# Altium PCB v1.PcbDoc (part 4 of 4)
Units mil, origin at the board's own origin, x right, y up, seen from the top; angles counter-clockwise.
Board outline 3043 x 5109 mil, 2 copper layers (Top Layer, Bottom Layer), stack 62 mil thick; 379 components, 219 nets, 963 pads, 1099 vias.
Unrouted connection lines stored in the file: 1.
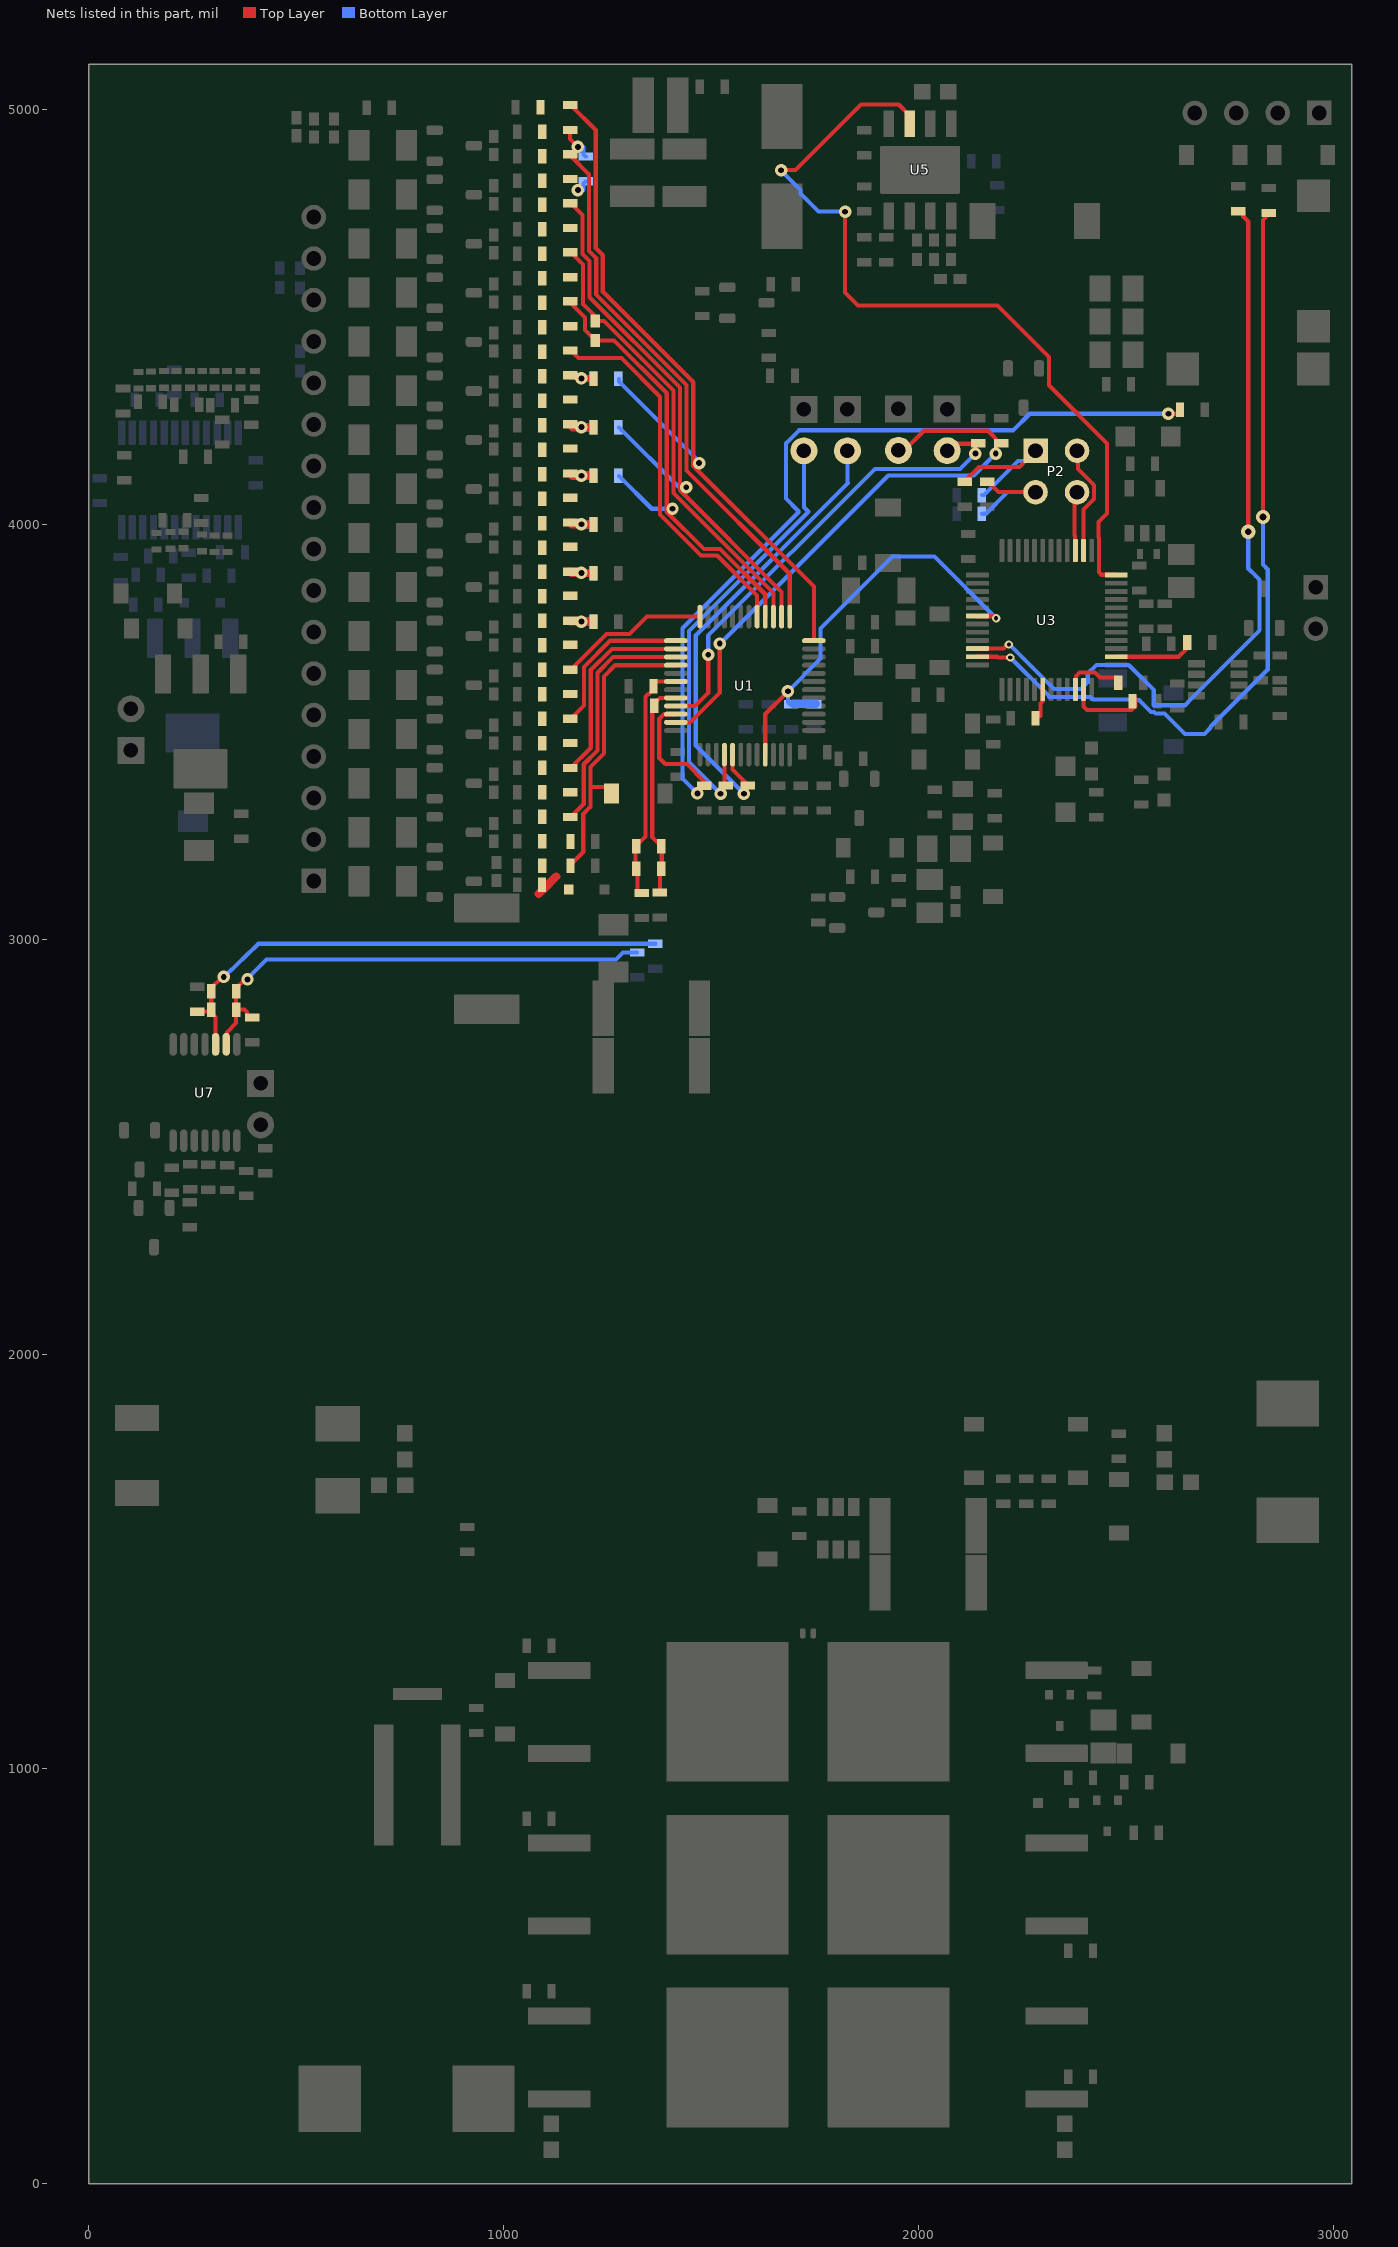
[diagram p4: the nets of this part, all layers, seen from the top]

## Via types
v1: diameter 30, hole 14, Top Layer to Bottom Layer, 1049 vias
v2: diameter 20, hole 10, Top Layer to Bottom Layer, 38 vias
v3: diameter 19.68, hole 7.87, Top Layer to Bottom Layer, tented both sides, 4 vias
v4: diameter 19.68, hole 7.87, Top Layer to Bottom Layer, 4 vias
v5: diameter 34, hole 16, Top Layer to Bottom Layer, 3 vias
v6: diameter 26, hole 10, Top Layer to Bottom Layer, 1 vias

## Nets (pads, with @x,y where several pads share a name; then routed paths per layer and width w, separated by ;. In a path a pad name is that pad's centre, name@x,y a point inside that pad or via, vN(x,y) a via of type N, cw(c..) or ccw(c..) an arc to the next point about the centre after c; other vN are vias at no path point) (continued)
POW_EN: U3.12 U5.3 | length 1975.5
  Top Layer w10: v1(1668,4853) 1668.94,4853.94 1703,4853.94 1860.41,5011.35 1951.56,5011.35 1978,4984.91 U5.3@1978,4965.22 ; v1(1822.41,4753.35) 1822.41,4558.35 1853.41,4527.35 2189.41,4527.35 2313.41,4403.35 2313.41,4334.97 2453.94,4194.45 2453.94,4026.25 2432.89,4005.2 2432.89,3968.38 2434.41,3966.86 2434.41,3884.35 2440.41,3878.35 2475.04,3878.35 U3.12@2475.95,3877.44
  Bottom Layer w10: v1(1668,4853) 1715.12,4805.88 1715.12,4796.64 1758.41,4753.35 v1@1809.41,4753.35
PTC_Pull: R97.2 U3.42 | length 81
  Top Layer w10: R97.2@2281.25,3532.04 2281.25,3532.9 2286.25,3537.9 2292.91,3537.9 2292.91,3567.78 2297.88,3572.75 2297.88,3600.95 U3.42@2298.78,3601.85
RXD: R101.2 U3.47 | length 192
  Top Layer w10: U3.47@2397.21,3601.85 2397.21,3560.55 2405.27,3552.49 2512.61,3552.49 2522.41,3562.29 R101.2@2522.41,3580.35
SBCLK: R107.1 U3.35 | length 1953.7
  Top Layer w10: U3.35@2141.3,3680.59 2188.55,3680.59 2190.14,3679 v2(2220.35,3679) ; v5(2829.41,4017.35) 2829.41,4733.33 R107.1@2844.88,4748.8
  Bottom Layer w10: v2(2220.35,3679) 2314.49,3584.87 2314.49,3583.65 2413.52,3583.65 2419.18,3578 2518.22,3578 2519.87,3576.35 2531.18,3576.35 2559.72,3547.8 2567.04,3547.8 2570.91,3543.94 2592.05,3543.94 2641.64,3494.35 2688.18,3494.35 2703.41,3509.58 2703.41,3512 2841,3649.59 2841,3891.13 2829.41,3902.72 v5(2829.41,4017.35)
SBIO: R108.1 U3.34 | length 1938.5
  Top Layer w10: U3.34@2141.3,3700.28 2204.57,3700.28 2214.29,3710 v2(2217,3710) ; R108.1@2769.41,4754.35 2776.91,4754.35 2781.91,4749.35 2781.91,4741.85 2794,4729.76 v5(2794,3982)
  Bottom Layer w10: v2(2217,3710) 2219.05,3710 2326.32,3602.74 2391.4,3602.74 2407.02,3618.35 2407.02,3639.97 2427.99,3660.95 2506.01,3660.95 2566.35,3600.61 2566.35,3563.8 2641.98,3563.8 2648.43,3570.25 2648.43,3571.35 ; 2648.42,3571.35 2821.41,3744.33 2821.41,3866.12 2813.41,3874.12 2794,3893.52 v5(2794,3982)
SCL: P2.1 R89.1 R104.2 | length 338.9
  Top Layer w10: R104.2@2110.41,4103.84 2144.91,4138.35 2242.41,4138.35 P2.1@2281.41,4177.35
  Bottom Layer w10: R89.1@2152.91,4070.35 2157.04,4070.35 2239.04,4152.35 P2.1@2256.41,4152.35
SCL_MCU: P2.2 U3.14 | length 267.9
  Top Layer w10: P2.2@2381.41,4177.35 2383.25,4175.5 2383.25,4132.82 2421.94,4094.13 2421.94,4060.56 2397.21,4035.83 U3.14@2397.21,3936.5
SDA: P2.3 R90.1 R103.2 | length 295.4
  Top Layer w10: R103.2@2165.41,4103.84 2191.91,4077.35 P2.3@2281.41,4077.35
  Bottom Layer w10: R90.1@2152.91,4025.35 2161.85,4025.35 2213.85,4077.35 P2.3@2281.41,4077.35 P2.3@2268.41,4064.35
SDA_MCU: P2.4 U3.15 | length 144.1
  Top Layer w10: U3.15@2377.52,3936.5 2376.62,3937.41 2376.62,3972.13 2375.55,3973.2 2375.55,4071.49 P2.4@2381.41,4077.35
SHUT: C25.1 R92.2 U1.33 U3.30 | length 1055.1
  Top Layer w10: U1.33@1629.96,3444.74 1629.96,3542.9 v1(1684.41,3597.35) ; U3.30@2141.3,3779.02 2142.21,3778.11 2178.94,3778.11 2183.7,3773.35 v2(2186.41,3773.35)
  Bottom Layer w10: C25.1@1692.79,3565.84 1689.41,3565.84 1684.41,3570.84 v1(1684.41,3597.35) 1763.41,3676.35 1763.41,3748.97 1936.78,3922.35 2037.41,3922.35 v2(2186.41,3773.35)
  Bottom Layer w20: C25.1@1696.79,3567.34 R92.2@1751.41,3567.34
SRN: C27.2 C29.2 C33.2 R87.2 U1.20 | length 524.8
  Top Layer w10: R87.2@1375.91,3113.84 1375.91,3164.85 1380.4,3169.35 1380.4,3223.35 1357.41,3246.34 1357.41,3562.35 1376.61,3581.55 U1.20@1414.41,3581.55
SRN1: C81.2 C83.2 C84.2 R165.2 U7.10 | length 1289.8
  Top Layer w10: C81.2@260.59,2825.35 289.59,2825.35 C84.2@294.59,2830.35 ; U7.10@305.18,2746.49 305.18,2812.26 294.59,2822.85 C84.2@294.59,2830.35 ; v1(325,2909) 321.74,2909 294.59,2881.85 C83.2@294.59,2874.35 C84.2@294.59,2830.35
  Bottom Layer w10: v1(325,2909) 408,2989 R165.2@1365,2989
SRP: C28.2 C29.1 C33.1 R88.2 U1.18 | length 578.7
  Top Layer w10: R88.2@1321.91,3113.84 1321.91,3164.85 1317.41,3169.35 1317.41,3223.35 1341.41,3247.35 1341.41,3584.4 1347.85,3590.85 1349.41,3590.85 1360.41,3601.85 C28.2@1360.41,3609.35 1360.41,3615.92 1365.41,3620.92 U1.18@1414.41,3620.92
SRP1: C82.2 C83.1 C84.1 R166.2 U7.9 | length 1199.2
  Top Layer w10: U7.9@330.77,2746.49 332.24,2747.97 332.24,2775.51 354.59,2797.85 C84.1@354.59,2830.35 ; v1(382,2903) 378.17,2899.17 371.91,2899.17 354.59,2881.85 C83.1@354.59,2874.35 C84.1@354.59,2830.35 ; C82.2@393.59,2811.35 386.09,2811.35 381.09,2816.35 381.09,2823.85 374.59,2830.35 C84.1@354.59,2830.35
  Bottom Layer w10: v1@381,2904 428,2951 1270,2951 1287,2968 R166.2@1321,2968
STB: R100.2 U3.2 | length 186.4
  Top Layer w10: U3.2@2475.95,3680.59 2626.16,3680.59 2646.41,3700.85 R100.2@2646.41,3708.35
TS1: C23.1 RT1.2 U1.21 | length 1161.7
  Top Layer w10: U1.21@1414.41,3561.87 1460.93,3561.87 1492.41,3593.35 v1(1492.41,3685.35) ; RT1.2@2068.41,4177.35 2084.93,4193.86 C23.1@2139.91,4193.86 ; v1(2136.41,4170.35) 2136.41,4190.36 C23.1@2139.91,4193.86 ; C23.1@2143.41,4193.86 C23.1@2139.91,4193.86
  Bottom Layer w10: v1(1492.41,3685.35) 1492.41,3731.35 1894.41,4133.35 2099.41,4133.35 v1(2136.41,4170.35)
TS2: C26.1 RT2.2 U1.23 | length 1410
  Top Layer w10: U1.23@1414.26,3522.35 U1.23@1414.41,3522.5 1448.93,3522.5 1520.41,3593.97 v1(1520.41,3712.35) ; RT2.2@1964.41,4177.35 2012.41,4225.35 2166.93,4225.35 2198.41,4193.86 2189.41,4193.86 2185.91,4190.36 2185.91,4170.85 v1(2185.41,4170.35)
  Bottom Layer w10: v1(1520.41,3712.35) 1521.41,3712.35 1926.41,4117.35 2132.41,4117.35 v1(2185.41,4170.35)
TS3: C32.1 RT3.2 U1.28 | length 1080.8
  Top Layer w10: v1(1522.41,3350.35) 1522.41,3365.35 1527.41,3370.35 C32.1@1534.41,3370.35 ; C32.1@1531.54,3374.72 U1.28@1531.54,3444.74
  Bottom Layer w10: v1(1522.41,3350.35) 1446.41,3426.35 1446.41,3742.72 1733.85,4030.15 1723,4041 RT3.2@1723,4177
TS4: C35.1 RT4.2 U1.29 | length 1144.3
  Top Layer w10: U1.29@1551.22,3444.74 1551.22,3408.97 1587.41,3372.78 1585.85,3372.78 1578.41,3365.35 1578.41,3356.14 1581.55,3353 1581.06,3353 v1(1578.41,3350.35)
  Bottom Layer w10: v1(1578.41,3350.35) 1462.41,3466.35 1462.41,3732.35 1829.53,4099.47 1828,4101 RT4.2@1828,4177
TXD: R102.2 U3.46 | length 140.6
  Top Layer w10: U3.46@2377.52,3601.85 2378.43,3602.76 2378.43,3633.51 2387.27,3642.35 2424.28,3642.35 2436.28,3630.35 R102.2@2478.41,3630.35
VC0: C1.1 D9.1 D10.1 R17.2 R18.2 U1.16 | length 836.8
  Top Layer w10: C1.1@1158.91,3177.35 1191.22,3209.65 1191.22,3302.03 1208.41,3319.22 1208.41,3367 ; D10.1@1259.53,3351 1259.53,3353.99 1246.52,3367 1208.41,3367 ; U1.16@1414.41,3660.29 1268.35,3660.29 1241.41,3633.35 1241.41,3447.88 1208.41,3414.88 1208.41,3367
  Top Layer w20: 1083.91,3108.91 1126,3151 R17.2@1095.25,3120.25
VC1: C2.2 C9.1 R19.2 R20.2 U1.15 | length 581.3
  Top Layer w10: C2.2@1159.41,3292.85 1192.41,3325.85 1192.41,3421.51 1225.41,3454.51 1225.41,3642.09 1263.29,3679.98 U1.15@1414.41,3679.98
VC2: C2.1 C3.2 R21.2 R22.2 U1.14 | length 484.4
  Top Layer w10: C3.2@1159.41,3411.14 1209.41,3461.14 1209.41,3648.72 1260.35,3699.66 U1.14@1414.41,3699.66
VC3: C3.1 C4.2 R23.2 R24.2 U1.13 | length 388.1
  Top Layer w10: C4.2@1159.41,3529.42 1193.41,3563.42 1193.41,3656.35 1256.41,3719.35 U1.13@1414.41,3719.35
VC4: C4.1 C5.2 R25.2 R26.2 U1.12 | length 366.8
  Top Layer w10: C5.2@1159.41,3647.71 1247.05,3735.35 1302.41,3735.35 1344.48,3777.42 U1.12@1472.48,3777.42
VC5: C5.1 C6.2 R27.2 R28.2 R67.1 R69.2 | length 83.6
  Top Layer w20: C6.2@1160.06,3765.35 v1(1186.68,3765.35) R69.2@1214.41,3765.35
  Bottom Layer w20: v1(1186.68,3765.35) R67.1@1215.91,3765.35
VC6: C6.1 C7.2 R29.2 R30.2 R64.1 R65.2 | length 87.3
  Top Layer w20: C7.2@1159.41,3885.77 1162.64,3882.55 v1(1186.68,3882.55) 1186.77,3882.45 1215.91,3882.45 R65.2@1215.91,3882.36
  Bottom Layer w20: v1(1186.68,3882.55) 1186.78,3882.45 1215.91,3882.45 R64.1@1215.91,3882.35
VC7: C7.1 C8.2 R31.2 R32.2 R66.1 R70.2 | length 88.1
  Top Layer w20: C8.2@1159.41,4004.06 1163.72,3999.75 v1(1186.68,3999.75) 1186.86,3999.56 1215.91,3999.56 R70.2@1215.91,3999.37
  Bottom Layer w20: v1(1186.68,3999.75) 1186.88,3999.55 1215.91,3999.55 R66.1@1215.91,3999.35
VC8: C8.1 C10.2 R33.2 R50.1 R51.2 R62.1 | length 88.8
  Top Layer w20: C10.2@1159.41,4122.35 1164.81,4116.95 v1(1186.68,4116.95) 1186.99,4116.63 1215.91,4116.63 R62.1@1215.91,4116.32
  Bottom Layer w20: v1(1186.68,4116.95) 1186.98,4116.65 1215.91,4116.65 R50.1@1215.91,4116.35
VC9: C10.1 C11.2 R49.1 R52.2 R53.2 R68.2 | length 79.1
  Top Layer w20: C11.2@1165.15,4233.4 R68.2@1214.41,4233.4
  Bottom Layer w20: v1(1186.68,4234.15) 1187.08,4233.75 1215.91,4233.75 R49.1@1215.91,4233.35
VC10: C11.1 C12.2 R48.1 R54.2 R55.2 R63.1 | length 89.7
  Top Layer w15: C12.2@1159.41,4358.92 1161.91,4356.42 1177.55,4356.42 1182.62,4351.35 v1(1186.68,4351.35) 1187.18,4350.85 1215.41,4350.85 R63.1@1215.91,4350.35
  Bottom Layer w15: v1(1186.68,4351.35) 1187.18,4350.85 1215.41,4350.85 R48.1@1215.91,4350.35
VC11: C12.1 C13.2 R56.2 R57.2 U1.5 | length 913.3
  Top Layer w10: C12.1@1159.41,4420.41 1179.48,4400.35 1283.41,4400.35 1376.41,4307.35 1376.41,4023.35 1475.41,3924.35 1514.15,3924.35 1610.28,3828.23 U1.5@1610.28,3777.42
VC12: C13.1 C14.2 R46.1 R50.2 R58.2 R59.2 U1.4 | length 1167
  Top Layer w10: C13.1@1159.41,4538.7 1159.41,4534.35 1195.41,4498.35 1195.41,4467.72 R46.1@1220.41,4442.72 1265.52,4442.72 1392.41,4315.84 1392.41,4029.97 1482.04,3940.35 1520.78,3940.35 1629.96,3831.17 U1.4@1629.96,3777.42
  Bottom Layer w10: R50.2@1277.4,4116.35 1356.4,4037.35 v1(1406.41,4037.35)
VC13: C14.1 C20.2 R46.2 R60.2 R79.2 U1.3 | length 1094.6
  Top Layer w10: C14.1@1159.41,4656.99 1190.41,4625.99 1190.41,4530.33 1220.41,4500.33 R46.2@1220.41,4489.97 1240.91,4489.97 1408.41,4322.46 1408.41,4075.35 1649.65,3834.11 U1.3@1649.65,3777.42
VC14: C20.1 C21.2 R35.2 R49.2 R80.2 R81.2 U1.2 | length 1467.8
  Top Layer w10: C20.1@1159.41,4775.27 1189.41,4745.27 1189.41,4651.35 1206.41,4634.35 1206.41,4547.09 1424.41,4329.09 1424.41,4081.97 1669.33,3837.05 U1.2@1669.33,3777.42
  Bottom Layer w10: v1(1178.41,4805.35) 1191.55,4805.35 1191.55,4821.35 1196.55,4826.35 R35.2@1197.41,4826.35 ; R49.2@1277.4,4233.35 1421.4,4089.35 v1(1439.41,4089.35)
VC15: C21.1 C22.2 R35.1 R82.2 R83.2 U1.1 | length 1419
  Top Layer w10: C21.1@1159.41,4889.35 1205.41,4843.35 1205.41,4658.72 1222.41,4641.72 1222.41,4553.72 1440.41,4335.72 1440.41,4129.35 1689.02,3880.74 U1.1@1689.02,3777.42 ; C22.2@1159.41,4950.35 1159.41,4928.35 v1(1178.41,4909.35)
  Bottom Layer w10: v1(1178.41,4909.35) 1178.76,4909 1191.55,4909 1191.55,4891.35 1196.55,4886.35 R35.1@1197.41,4886.35
VC16: C22.1 R48.2 R84.2 U1.48 | length 1818.9
  Top Layer w10: C22.1@1159.41,5011.84 1221.41,4949.84 1221.41,4665.35 1238.41,4648.35 1238.41,4560.35 1456.41,4342.35 1456.41,4140.35 1747.09,3849.67 U1.48@1747.09,3719.35
  Bottom Layer w10: R48.2@1277.4,4350.35 1277.4,4344.35 1470.41,4151.35 v1(1470.41,4147.35)
WAKE: C17.1 R71.2 U1.22 | length 2282
  Top Layer w10: U1.22@1414.41,3542.18 1386.24,3542.18 1374.41,3530.35 1374.41,3436.35 1388.87,3421.89 1440.87,3421.89 1482.75,3380.01 C17.1@1482.75,3371.57 ; v1(1466.41,3351.35) 1466.41,3356.76 1470.25,3360.6 1470.25,3365.08 1475.25,3370.08 C17.1@1482.75,3370.08 ; v1(2601.41,4266.35) 2624.41,4266.35 2629.41,4271.35 R71.2@2629.41,4276.35
  Bottom Layer w10: v1(1466.41,3351.35) 1430.41,3387.35 1430.41,3749.35 1709.41,4028.35 1709.41,4031.96 1679.5,4061.87 1679.5,4195.02 1710.83,4226.35 2227.41,4226.35 2267.41,4266.35 v1(2601.41,4266.35)
pads on no net: RT5.1S RT5.2S U1.19 U1.40 U1.44 U3.1 U3.3 U3.5 U3.9 U3.10 U3.11 U3.16 U3.17 U3.18 U3.19 U3.20 U3.21 U3.22 U3.23 U3.24 U3.31 U3.32 U3.33 U3.36 U3.37 U3.39 U3.40 U3.41 U5.6 U5.9@2003,4854 U6.1 U6.15 U6.16 U7.1 U7.3 U7.12 U7.13 U7.14

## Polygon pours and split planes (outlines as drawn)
NetQ1_3 on Top Layer "TOP_LAYER_NETQ1_3_P123" (solid, pour order 123): 717,3187.17 800,3187.17 800,3099.17 799,3098.17 715,3098.17 715,3186.17 717,3188.17
NetQ2_3 on Top Layer "TOP_LAYER_NETQ2_3_P122" (solid, pour order 122): 717,3305.43 800,3305.43 800,3217.43 799,3216.43 715,3216.43 715,3304.43 717,3306.43
NetQ3_3 on Top Layer "TOP_LAYER_NETQ3_3_P121" (solid, pour order 121): 717,3423.68 800,3423.68 800,3335.68 799,3334.68 715,3334.68 715,3422.68 717,3424.68
NetQ4_3 on Top Layer "TOP_LAYER_NETQ4_3_P120" (solid, pour order 120): 717,3541.94 800,3541.94 800,3453.94 799,3452.94 715,3452.94 715,3540.94 717,3542.94
NetQ5_3 on Top Layer "TOP_LAYER_NETQ5_3_P119" (solid, pour order 119): 717,3660.2 800,3660.2 800,3572.2 799,3571.2 715,3571.2 715,3659.2 717,3661.2
NetQ6_3 on Top Layer "TOP_LAYER_NETQ6_3_P118" (solid, pour order 118): 717,3778.46 800,3778.46 800,3690.46 799,3689.46 715,3689.46 715,3777.46 717,3779.46
NetQ7_3 on Top Layer "TOP_LAYER_NETQ7_3_P117" (solid, pour order 117): 717,3896.71 800,3896.71 800,3808.71 799,3807.71 715,3807.71 715,3895.71 717,3897.71
NetQ8_3 on Top Layer "TOP_LAYER_NETQ8_3_P116" (solid, pour order 116): 717,4014.97 800,4014.97 800,3926.97 799,3925.97 715,3925.97 715,4013.97 717,4015.97
NetQ9_3 on Top Layer "TOP_LAYER_NETQ9_3_P115" (solid, pour order 115): 717,4133.23 800,4133.23 800,4045.23 799,4044.23 715,4044.23 715,4132.23 717,4134.23
NetQ10_3 on Top Layer "TOP_LAYER_NETQ10_3_P114" (solid, pour order 114): 717,4251.49 800,4251.49 800,4163.49 799,4162.49 715,4162.49 715,4250.49 717,4252.49
NetQ11_3 on Top Layer "TOP_LAYER_NETQ11_3_P113" (solid, pour order 113): 717,4369.74 800,4369.74 800,4281.74 799,4280.74 715,4280.74 715,4368.74 717,4370.74
NetQ16_3 on Top Layer "TOP_LAYER_NETQ16_3_P112" (solid, pour order 112): 717,4961.03 800,4961.03 800,4873.03 799,4872.03 715,4872.03 715,4960.03 717,4962.03
NetQ15_3 on Top Layer "TOP_LAYER_NETQ15_3_P111" (solid, pour order 111): 717,4842.77 800,4842.77 800,4754.77 799,4753.77 715,4753.77 715,4841.77 717,4843.77
NetQ14_3 on Top Layer "TOP_LAYER_NETQ14_3_P110" (solid, pour order 110): 717,4724.51 800,4724.51 800,4636.51 799,4635.51 715,4635.51 715,4723.51 717,4725.51
NetQ13_3 on Top Layer "TOP_LAYER_NETQ13_3_P109" (solid, pour order 109): 717,4606.26 800,4606.26 800,4518.26 799,4517.26 715,4517.26 715,4605.26 717,4607.26
NetQ12_3 on Top Layer "TOP_LAYER_NETQ12_3_P108" (solid, pour order 108): 717,4488 800,4488 800,4400 799,4399 715,4399 715,4487 717,4489
GND on Top Layer "Top Layer-No Net 19" (solid, remove dead copper, pour order 68): 1830.41,4788.35 1699.41,4657.35 1256.41,4657.35 1256.41,4817.35 1680.41,4817.35 1788.9,4925.84 2075.41,4927.35 2075.41,4788.35
GND on Top Layer "Bottom Layer-No Net" (solid, remove dead copper, pour order 124): -6.95,5089.2 3015.64,5089.2 3015.64,1767 -6.95,1767
GND on Top Layer "Top Layer-No Net 23" (solid, remove dead copper, pour order 82): 1612.14,4630.35 1294.41,4630.35 1294.41,4087.35 1612.14,4087.35
BAT- on Top Layer "TOP_LAYER_BAT-_P107" (solid, pour order 107): 460,2988 1286,2988 1286,1781 460,1781
GND on Top Layer "Top Layer-No Net 15" (solid, pour order 94): 1875.41,3872.35 1875.41,3685.35 2076.41,3685.35 2088.41,3673.35 2088.41,3422.35 2108.41,3402.35 2148.41,3402.35 2148.41,3872.35
NetQ30_2 on Top Layer "TOP_LAYER_NETQ30_2_P105" (solid, pour order 105): 338,3298 338,3684.72 337.35,3685.37 240,3685.37 240,3581 194,3535 194,3298
GND on Top Layer "Top Layer-No Net 4" (solid, remove dead copper, pour order 26): 2178.41,2999.35 2178.41,3612.35 2178.41,4165.35 2708.41,4165.35 2708.41,3682.35 2321.41,3682.35 2321.41,2999.35
GND on Top Layer "Top Layer-No Net 13" (solid, remove dead copper, pour order 44): 1202.41,3289.35 1202.41,3784.35 1768.41,3784.35 1768.41,3429.35 1330.41,3429.35 1330.41,3289.35
GND on Top Layer "Top Layer-No Net 14" (solid, remove dead copper, pour order 46): 1408.89,3015.35 1408.89,3261.35 1370.41,3261.35 1370.41,3411.35 1836.41,3411.35 1836.41,3015.35
GND on Top Layer "Top Layer-No Net 3" (solid, remove dead copper, pour order 60): 1202.41,2995 1202.41,3330.35 1330.41,3330.35 1330.41,3248.05 1311.86,3248.05 1311.86,2995
3V3 on Top Layer "TOP_LAYER_3V3_P002" (solid, pour order 2): 2522.2,3791.56 2554.37,3792.66 2554.15,3864.94 2544.76,4014 2615.28,4011.68 2607.41,3880.35 2606.41,3879.35 2679.41,3879.35 2679.41,3728.86 2521.87,3728.86
NetC54_1 on Top Layer "TOP_LAYER_NETC54_1_P104" (solid, pour order 104): 2343.41,4779.35 2345.41,4777.35 2448.41,4777.35 2448.41,4750.35 2481.41,4717.35 2481.41,4317.66 2407.09,4317.66 2404.41,4320.35 2404.41,4651.35 2349.41,4651.35 2346.41,4648.35 2343.41,4651.35 2343.41,4778.35
NetD31_1 on Top Layer "Top Layer-No Net 7" (solid, remove dead copper, pour order 32): 1080.41,1391.35 1080.41,1127.35 914.41,1127.35 914.41,1223.35 962.41,1271.35 962.41,1391.35
NetC47_1 on Top Layer "Top Layer-No Net 16" (solid, remove dead copper, pour order 80): 1362.41,4878.35 1362.41,5077.35 1204.41,5077.35 1204.41,5062.35 1256.41,5010.35 1256.41,4878.35
NetC48_1 on Top Layer "Top Layer-No Net 17" (solid, remove dead copper, pour order 64): 1393.41,5077.35 1393.41,4878.35 1501.41,4878.35 1501.41,5077.35
PACK+ on Top Layer "Top Layer-No Net 11" (solid, remove dead copper, pour order 42): 3015.41,118.35 3015.41,260.35 3015.41,1657.35 2106.41,1657.35 2106.41,118.35
NetC60_2 on Top Layer "Top Layer-No Net 10" (solid, remove dead copper, pour order 38): 848.41,1111.79 1287.41,1111.79 1287.41,17.35 848.41,17.35
PACK- on Top Layer "Top Layer-No Net 9" (solid, pour order 36): 1445.41,2995.35 1445.41,1786.35 3016.41,1786.35 3016.41,2995.35
BAT+ on Top Layer "Top Layer-No Net 6" (solid, pour order 28): 0,1711 0,11.35 825.41,11.35 825.41,1017.35 727,1115.76 727,1711
NetD33_1 on Top Layer "Top Layer-No Net 1" (solid, pour order 6): 1782.41,1550.35 1751.41,1581.35 1608.41,1581.35 1608.41,1488.35 1782.41,1488.35
NetD37_1 on Top Layer "Top Layer-No Net" (solid, remove dead copper, pour order 84): 2519.95,1064.87 2519.95,949.35 2389.41,949.35 2389.41,1064.87
NetQ24_1 on Top Layer "Top Layer-No Net 8" (solid, remove dead copper, pour order 90): 1789.41,1705.35 1789.41,1381.35 1992.41,1381.35 1992.41,1705.35
NetD33_1 on Top Layer "Top Layer-No Net 12" (solid, remove dead copper, pour order 92): 2090.41,49.35 2090.41,1338.35 2060.41,1368.35 1651.41,1368.35 1519.41,1500.35 1519.41,1665.35 1455.41,1729.35 1313.41,1729.35 1313.41,49.35
GND on Bottom Layer "Bottom Layer-No Net" (solid, remove dead copper, pour order 106): 0,5082.24 3022.59,5082.24 3022.59,1770 0,1770
GND on Bottom Layer "Bottom Layer-No Net 1" (solid, remove dead copper, pour order 98): 2145.41,4641.35 1533.41,4641.35 1533.41,5072.35 2145.41,5072.35
NetQ31_2 on Bottom Layer "BOTTOM_LAYER_NETQ31_2_P052" (solid, pour order 52): 198,3773 202.05,3768.95 202.05,3645.48 178.32,3645.48 175.19,3642.35 176,3641.54 176,3371 337,3371 340.78,3374.78 340.78,3651.79 287.21,3651.79 283,3656 283,3774 198,3774
GND on Bottom Layer "Bottom Layer-No Net 3" (solid, remove dead copper, pour order 34): 1285.41,3193.35 1213.41,3193.35 1213.41,3014.35 1285.41,3014.35
GND on Bottom Layer "Bottom Layer-No Net 6" (solid, remove dead copper, pour order 74): 1218.41,5045.35 1306.41,4957.35 1306.41,4640.35 1474.41,4640.35 1474.41,5074.35 1218.41,5074.35
PACK- on Bottom Layer "Top Layer-No Net 9" (solid, pour order 102): 1391,2995.35 1391,1789.35 3016.41,1789.35 3016.41,2995.35
NetD33_1 on Bottom Layer "Bottom Layer-No Net 2" (solid, remove dead copper, pour order 88): 1197.41,1726.35 1071.41,1600.35 1071.41,17.35 2393.41,17.35 2393.41,1359.35 1639.41,1359.35 1622.41,1376.35 1622.41,1571.35 1467.41,1726.35

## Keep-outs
Keep-Out Layer:
  text ".Layer_Name" at 577,-858.49 h60

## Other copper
Top Layer:
  rectangle net NetD33_2: 1609.41,1602.35 1782.41,1653.35
  rectangle net CANL: 2919.41,3718.35 3026.41,3778.35
  rectangle net CANH: 2919.41,3818.35 3026.41,3878.35
  rectangle net VC0: 1073.91,3096.84 1177.91,3197.84
  rectangle net VC1: 1074.41,3213.84 1178.41,3314.84
  rectangle net VC0: 1073.41,3099.35 1114.41,3196.35
  rectangle net VC2: 1074.41,3330.63 1178.41,3431.63
  rectangle net VC3: 1074.41,3448.92 1178.41,3549.92
  rectangle net VC4: 1074.41,3567.2 1178.41,3668.2
  rectangle net VC5: 1074.41,3685.49 1178.41,3786.49
  rectangle net VC6: 1074.41,3803.78 1178.41,3904.78
  rectangle net VC7: 1074.41,3922.06 1178.41,4023.06
  rectangle net VC8: 1074.41,4040.35 1178.41,4141.35
  rectangle net VC9: 1074.41,4158.63 1178.41,4259.63
  rectangle net VC10: 1074.41,4276.92 1178.41,4377.92
  rectangle net VC11: 1074.41,4395.2 1178.41,4496.2
  rectangle net VC12: 1074.41,4513.49 1178.41,4614.49
  rectangle net VC13: 1074.41,4631.78 1178.41,4732.78
  rectangle net VC14: 1074.41,4750.06 1178.41,4851.06
  rectangle net VC15: 1074.41,4868.35 1178.41,4969.35
  rectangle net VC16: 1074.41,4986.35 1178.41,5031.35
  text ".Layer_Name" at 577,-858.49 h60
Bottom Layer:
  rectangle net GND: 1873.41,4804.35 2074.41,4903.35
  rectangle net NetQ24_1: 1648.41,1379.69 1989.41,1684.35
  rectangle net BAT-: 456.41,1803 1300,2940
  rectangle net NetQ16_3: 706.41,4869.35 1155.41,4968.86
  rectangle net NetQ15_3: 688.41,4741.6 1155.41,4843.35
  rectangle net NetQ6_3: 689.41,3678.29 1162.41,3787.29
  rectangle net NetQ7_3: 688.41,3796.55 1162.41,3905.55
  rectangle net NetQ8_3: 688.41,3914.8 1162.41,4023.8
  rectangle net NetQ9_3: 688.41,4033.06 1162.41,4142.06
  rectangle net NetQ10_3: 688.41,4151.32 1162.41,4260.32
  rectangle net NetQ11_3: 688.41,4269.57 1162.41,4378.57
  rectangle net NetQ5_3: 689.41,3559.03 1160,3668.03
  rectangle net NetQ4_3: 689.41,3440.77 1159.41,3549.77
  rectangle net NetQ3_3: 689.41,3322.52 1159.41,3431.52
  rectangle net NetQ2_3: 689.41,3204.26 1162,3313.26
  rectangle net NetQ1_3: 689.41,3086 1160,3195
  rectangle net NetQ13_3: 688.41,4505.09 1201.41,4614.09
  rectangle net NetQ14_3: 688.41,4623.35 1240.41,4732.35
  rectangle net NetQ12_3: 688.41,4386.83 1201.41,4495.83
  rectangle net PACK+: 2016.41,1379.35 2393.41,1684.35
  text ".Layer_Name" at 577,-858.49 h60

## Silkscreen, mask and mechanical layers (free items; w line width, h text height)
Top Overlay:
  text "SCL" at 2297.41,4240.35 h30
  text "PACK-" at 2773.41,2540.35 h60 r270
  text "BAT-" at 701.41,2299.35 h60 r90
  text "PACK+" at 2776.41,811.35 h60 r270
  text "BAT+" at 696.41,492.35 h60 r90
  text ".Layer_Name" at 577,-858.49 h60
Bottom Overlay:
  text "CAUTION" at 983.41,226.35 h60
  text "READ USER GUIDE" at 1086.41,162.35 h60
  text "BEFORE USE" at 1010.41,95.35 h60
  text ".Layer_Name" at 577,-858.49 h60
Top Paste:
  rectangle: 2919.41,3718.35 3026.41,3778.35
  rectangle: 2919.41,3818.35 3026.41,3878.35
  rectangle: 2867.41,2158.35 3008.41,2685.35
  rectangle: 463.41,2150.35 604.41,2677.35
  rectangle: 460.41,455.35 601.41,982.35
  rectangle: 2866.41,455.35 3007.41,982.35
  text ".Layer_Name" at 577,-858.49 h60
Bottom Paste:
  text ".Layer_Name" at 577,-858.49 h60
Top Solder:
  rectangle: 2919.41,3718.35 3026.41,3778.35
  rectangle: 2919.41,3818.35 3026.41,3878.35
  rectangle: 2867.41,2158.35 3008.41,2685.35
  rectangle: 463.41,2150.35 604.41,2677.35
  rectangle: 460.41,455.35 601.41,982.35
  rectangle: 2866.41,455.35 3007.41,982.35
  text ".Layer_Name" at 577,-858.49 h60
  text ".Layer_Name" at 577,-858.49 h60
Bottom Solder:
  text ".Layer_Name" at 577,-858.49 h60
Drill Guide:
  text ".Layer_Name" at 577,-858.49 h60
M1 Board Outline:
  the board outline again, w10
  text ".Layer_Name" at 577,-858.49 h60
M2 Board Dimensions:
  rectangle: 0,-275 125,-150
  rectangle: 125,-400 500,-275
  lines w7: 0,-275 1000,-275 ; 125,-400 125,-150 ; 250,-400 250,-150 ; 500,-400 500,-150 ; 750,-400 750,-150 ; 0,-400 1000,-400 1000,-150 0,-150 0,-400
  text ".Layer_Name" at 577,-858.49 h60
M3 3D STEP Top:
  text ".Layer_Name" at 577,-858.49 h60
M4 3D STEP Bottom:
  text ".Layer_Name" at 577,-858.49 h60
M5 Assembly Top:
  lines w10: -292,-930.17 6308,-930.17 ; -292,-726.83 6310,-726.83 ; -292,-523.5 -292,-1133.5 3713,-1133.5 6310,-1133.5 6310,-523.5 -291.5,-523.5 -291.5,-1133.5 1284,-1133.5 ; 2173,-1133.5 2173,-523.5 ; 3440,-726.83 3440,-523.5 ; 4280,-726.83 4280,-523.5 ; 4902,-1140 4902,-937.17
  text "COMPONENTS MARKED 'DNP' SHOULD NOT BE POPULATED." at 1153.5,-318.5 h60
  text "ASSEMBLY VARIANT:" at 1153,-434 h60
  text ".VariantName" at 2189,-434 h60
  text "PCB VIEWED FROM TOP SIDE" at -228.5,-655.67 h60
  text "BOARD #:" at 2248,-655.67 h60
  text ".PRJ_Number" at 2793.5,-655.67 h60
  text "REV:" at 3638,-655.67 h60
  text ".PCB_Rev" at 3929.5,-655.67 h60
  text "SVN REV:" at 4476,-655.67 h60
  text ".VersionControl_RevNumber" at 4982,-655.67 h60
  text "TID #:" at 2248,-859 h60
  text ".TID" at 2793.5,-859 h60
  text "PLOT NAME =" at -228.5,-1064.34 h60
  text ".plot_File_Name" at 577,-1064.34 h60
  text "GENERATED    :" at 2250,-1064.34 h60
  text ".Print_Date" at 3119.5,-1064.34 h60
  text ".Print_Time" at 3848.5,-1064.34 h60
  text "TEXAS INSTRUMENTS" at 5113,-1064.34 h60
M6 Assembly Bottom:
  lines w10: -292.5,-727.33 6309.5,-727.33 ; -290.5,-930.67 6309.5,-930.67 ; 1115.5,-1140.5 1115.5,-937.67 ; 1737.5,-727.33 1737.5,-524 ; 2577.5,-727.33 2577.5,-524 ; 3844.5,-1134 3844.5,-524 ; 4733.5,-1134 6309,-1134 6309,-524 -292.5,-524 -292.5,-1134 2304.5,-1134 6309.5,-1134 6309.5,-524
  text "COMPONENTS MARKED 'DNP' SHOULD NOT BE POPULATED." at 6102,-318 h60
  text ".VariantName" at 5058,-434 h60
  text "ASSEMBLY VARIANT:" at 6097,-434 h60
  text ".VersionControl_RevNumber" at 1035.5,-656.17 h60
  text "SVN REV:" at 1541.5,-656.17 h60
  text ".PCB_Rev" at 2088,-656.17 h60
  text "REV:" at 2379.5,-656.17 h60
  text ".PRJ_Number" at 3224,-656.17 h60
  text "BOARD #:" at 3769.5,-656.17 h60
  text "PCB VIEWED FROM BOTTOM SIDE" at 6246,-656.17 h60
  text ".TID" at 3224,-859.5 h60
  text "TID #:" at 3769.5,-859.5 h60
  text "TEXAS INSTRUMENTS" at 904.5,-1064.84 h60
  text ".Print_Time" at 2169,-1064.84 h60
  text ".Print_Date" at 2898,-1064.84 h60
  text "GENERATED    :" at 3767.5,-1064.84 h60
  text ".plot_File_Name" at 5440.5,-1064.84 h60
  text "PLOT NAME =" at 6246,-1064.84 h60
M9 Title Sheet:
  drawing of 57 lines, arcs and shapes, not listed
  text "1" at 739.84,8036.5 h70
  text "2" at 3235.5,8036.5 h70
  text "3" at 5724.84,8036.5 h70
  text "4" at 8231.51,8036.5 h70
  text "5" at 10730.5,8036.5 h70
  text "6" at 13235.5,8036.5 h70
  text "A" at -416.5,6893.5 h70
  text "A" at 14383.5,6893.5 h70
  text "B" at -416.5,4513.5 h70
  text "B" at 14383.5,4513.5 h70
  text "C" at -416.5,2138.5 h70
  text "C" at 14383.5,2138.5 h70
  text "PROJECT TITLE:" at 11343.5,277.5 h45
  text ".PRJ_Title" at 11393.5,144.17 h70
  text "DESIGNED FOR:" at 11343.5,-23.5 h45
  text ".PRJ_Customer" at 11393.5,-163.5 h70
  text "D" at -416.5,-231.5 h70
  text "D" at 14383.5,-231.5 h70
  text "FILE NAME:" at 11343.5,-323.5 h45
  text ".PCB_File_Name_No_Path" at 11393.5,-443.5 h70
  text "Texas Instruments (TI) and/or its licensors do not warrant the accuracy or completeness of this specification" at 6374,-605.34 h45
  text "ENGINEER:" at 11343.5,-613.5 h45
  text "LAYOUT BY:" at 12848.5,-613.5 h45
  text "or any information contained therein. TI and/or its licensors do not warrant that this design will meet" at 6329.01,-718 h45
  text ".PRJ_Engineer" at 11393.5,-768.49 h70
  text ".PCB_Layout" at 12899,-768.49 h70
  text "the specifications, will be suitable for your application or fit for any particular purpose, or will operate in" at 6329.01,-830.67 h45
  text ".Layer_Name" at 577,-858.49 h60
  text "ALTIUM DESIGNER VERSION:" at 12848.5,-923.5 h45
  text "an implementation. TI and/or its licensors do not warrant that the design is production worthy. You should" at 6329.01,-943.33 h45
  text "completely validate and test your design implementation to confirm the system functionality for your application." at 6374,-1056 h45
  text ".print_Scale" at 11393.5,-1056.83 h70
  text ".Application_BuildNumber" at 12899,-1056.83 h70
  text "1" at 739.84,-1263.5 h70
  text "2" at 3235.5,-1263.5 h70
  text "3" at 5724.84,-1263.5 h70
  text "4" at 8231.51,-1263.5 h70
  text "5" at 10730.5,-1263.5 h70
  text "6" at 13235.5,-1263.5 h70
M10 Fab Notes:
  drawing of 189 lines, arcs and shapes, not listed
  text "DESIGN INFORMATION" at 12382.02,6356.17 h60
  text "MIN. TRACK WIDTH:" at 11737.46,6224.05 h60
  text "8" at 12833.7,6224.05 h60
  text "MIL" at 12988.46,6224.05 h60
  text "MIN. CLEARANCE:" at 11737.46,6099.92 h60
  text "0.2" at 12773.7,6099.93 h60
  text "mm" at 12988.46,6099.92 h60
  text "MIN. VIA PAD SIZE:" at 11737.46,5975.8 h60
  text "24" at 12803.71,5975.8 h60
  text "MIL" at 12988.46,5975.8 h60
  text "0.05mm (2MIL)" at 12432.46,5845.9 h60
  text "MINIMUM ANNULAR RING" at 11408.23,5837.67 h60
  text "EXTERNAL" at 13140.46,5837.67 h60
  text "PER" at 11608.23,5727.55 h60
  text "IPC-D-275 CLASS 2 LEVEL C" at 11828.23,5727.54 h60
  text "MIL, HOLES" at 13316.46,5627.07 h60
  text "+/-" at 12924,5618.48 h60
  text "+/-" at 13778,5618.48 h60
  text "REGISTRATION TOLERANCES:" at 11408.23,5617.42 h60
  text "METAL" at 12608,5617.42 h60
  text "5" at 13184.2,5617.42 h60
  text "3" at 14017.2,5617.42 h60
  text "MIL" at 14133.46,5617.42 h60
  text "HOLE SIZE TOLERANCE (UNLESS OTHERWISE SPECIFIED):" at 11408.23,5519.1 h60
  text "+/-" at 13778,5516.23 h60
  text "3" at 14017.2,5515.17 h60
  text "MIL" at 14133.46,5515.17 h60
  text "MATERIAL:" at 11333.46,5377.52 h60
  text "FR-4 High Tg" at 12319.9,5249 h60
  text "X" at 12175.46,5241.01 h60
  text "FR-408" at 11754.46,5236.49 h60
  text "OTHER" at 13242.46,5236.49 h60
  text "62 MIL (1.6mm) +/-10%" at 12074.56,5093.46 h60
  text "X" at 11954.46,5091.01 h60
  text "THICKNESS:" at 11408.23,5085.24 h60
  text "OTHER" at 13359.46,5085.24 h60
  text "TOLERANCE:" at 11408.23,4946.92 h60
  text "X" at 12256.46,4946.92 h60
  text "ANSI IPC-6012 TYPE 3 CLASS 2" at 12434.48,4946.92 h60
  text "OTHER +/-" at 12434.46,4802.73 h60
  text "BOW & TWIST:" at 11408.23,4657.54 h60
  text "X" at 12256.46,4657.54 h60
  text "ANSI IPC-6012 TYPE 3 CLASS 2" at 12434.48,4657.54 h60
  text "OTHER +/-" at 12434.46,4510.85 h60
  text "DRILLING:" at 11333.46,4380.23 h60
  text "NC_DRILL FILES" at 13094.46,4275.04 h60
  text "REFERENCE:" at 11408.23,4271.1 h60
  text "X" at 12065.46,4271.01 h60
  text "AS SHOWN" at 12243.46,4271.1 h60
  text "X" at 12966.46,4271.1 h60
  text "OTHER" at 13392.46,4128.85 h60
  text "PTH COPPER THICKNESS:" at 11407.91,4125.32 h60
  text "X" at 12547.14,4125.32 h60
  text "20-30 um" at 12675.14,4125.32 h60
  text "BOARD FINISH:" at 11333.46,3977.73 h60
  text "SILKSCREEN:" at 11488.68,3867.6 h60
  text "X" at 12446.46,3867.6 h60
  text "TOP" at 12563.46,3867.6 h60
  text "X" at 12956.46,3867.6 h60
  text "BOTTOM" at 13074.46,3867.6 h60
  text "SILKSCREEN COLOR:" at 11488.68,3712.41 h60
  text "X" at 12445.46,3712.41 h60
  text "WHITE" at 12563.46,3712.41 h60
  text "OTHER" at 13074.46,3712.41 h60
  text "X" at 12576.46,3568.96 h60
  text "GREEN" at 12694.46,3568.96 h60
  text "OTHER" at 13312.46,3568.96 h60
  text "SOLDER RESIST COLOR:" at 11488.68,3562.1 h60
  text "X" at 12576.46,3414.71 h60
  text "MATTE" at 12694.46,3414.71 h60
  text "SEMI-GLOSS" at 13312,3414.07 h60
  text "IMMERSION GOLD (ENIG)" at 12394.46,3241.94 h60
  text "ENEPIG" at 13732,3234.72 h60
  text "SURFACE FINISH:" at 11333.46,3233.72 h60
  text "X" at 12216.46,3233.72 h60
  text "IMM. TIN/SILVER OR EQUIV" at 11663,3096.4 h60
  text "OTHER" at 13094.46,3092.47 h60
  text "ARRAY/PANEL:" at 11333.46,2937.09 h60
  text "CUT AND TRIM PER M1 BOARD OUTLINE" at 12394.46,2928.87 h60
  text "N.C. ROUTE" at 12394.46,2792.9 h60
  text "X" at 13082.46,2792.9 h60
  text "V. SCORE" at 13260.46,2792.9 h60
  text "CERTIFICATION:" at 11333.46,2663.77 h60
  text "MATERIALS AND WORKMANSHIP FOR ALL PCBS" at 12058.46,2663.77 h60
  text "TO MEET OR EXCEED THE REQUIREMENTS OF:" at 12058.46,2569.71 h60
  text "X" at 11695.97,2441.08 h60
  text "ANSI IPC-A-600F CLASS ->" at 11823.96,2441.08 h60
  text "X" at 13471.97,2441.08 h60
  text "2" at 13581.96,2441.08 h60
  text "1" at 13266.96,2439.58 h60
  text "3" at 13935.96,2439.58 h60
  text "X" at 12507.97,2293.39 h60
  text "RoHS" at 12635.96,2293.39 h60
  text "OTHER" at 13280.36,2293.39 h60
  text "PER ORDER" at 13677.42,2293.39 h60
  text "ALL BOARDS MUST MEET OR EXCEED UL94-V0 REQUIREMENTS." at 11361,2139.57 h60
  text "PCB MUST BEAR THE UL94V-0 UL REGISTERED MATERIAL ID NUMBER" at 11361,2023.5 h60
  text "ADDITIONAL REQUIREMENTS:" at 11333.46,1854.08 h60
  text "MICROSECTION:" at 11408.23,1746.95 h60
  text "YES" at 12313.96,1746.95 h60
  text "REQUIRED" at 13175.46,1602.62 h60
  text "BARE BOARD ELEC. TEST:" at 11408.23,1599.76 h60
  text "NONE" at 12713.96,1599.76 h60
  text "X" at 13057.46,1599.76 h60
  text "PER ORDER" at 13767.46,1599.76 h60
  text "XX MIL VIAS REQUIRE NON-CONDUCTIVE FILL AND PLANARIZE" at 11576.38,1394.82 h59
  text "XX MIL VIAS REQUIRE CONDUCTIVE FILL AND PLANARIZE" at 11584.38,1290.84 h60
  text "OUTER XX MIL TRACES REQUIRE 50 OHM SINGLE-ENDED IMPEDANCE" at 11583.39,1127.46 h58
  text "LAYER 2 & 3 (INNER LAYERS) XX MIL WIDE, XX MIL SPACE / TRACES REQUIRE 100 OHM DIFFERENTIAL IMPEDANCE" at 11575.39,891.74 h60
  text ".Layer_Name" at 577,-858.49 h60
M11 Gerber Information:
  lines w10: -292,-930.17 6308,-930.17 ; -292,-726.83 6310,-726.83 ; -292,-523.5 -292,-1133.5 3713,-1133.5 6310,-1133.5 6310,-523.5 -291.5,-523.5 -291.5,-1133.5 1284,-1133.5 ; 2173,-1133.5 2173,-523.5 ; 3440,-726.83 3440,-523.5 ; 4280,-726.83 4280,-523.5 ; 4902,-1140 4902,-937.17
  text "ALL ARTWORK VIEWED FROM TOP SIDE" at -228.5,-655.67 h60
  text "BOARD #:" at 2248,-655.67 h60
  text ".PRJ_Number" at 2793.5,-655.67 h60
  text "REV:" at 3638,-655.67 h60
  text ".PCB_Rev" at 3929.5,-655.67 h60
  text "SVN REV:" at 4476,-655.67 h60
  text ".VersionControl_RevNumber" at 4982,-655.67 h60
  text "LAYER NAME =" at -228.5,-858.49 h60
  text "TID #:" at 2248,-859 h60
  text ".TID" at 2793.5,-859 h60
  text "PLOT NAME =" at -228.5,-1064.34 h60
  text ".plot_File_Name" at 577,-1064.34 h60
  text "GENERATED    :" at 2250,-1064.34 h60
  text ".Print_Date" at 3119.5,-1064.34 h60
  text ".Print_Time" at 3848.5,-1064.34 h60
  text "TEXAS INSTRUMENTS" at 5113,-1064.34 h60
M12 Stackup:
  drawing of 530 lines, arcs and shapes, not listed
  text "Layer" at 9807.84,7852.5 h60
  text "Name" at 10217.76,7852.5 h60
  text "Material" at 11147.5,7852.5 h60
  text "Thickness" at 12007.27,7852.5 h60
  text "Constant" at 12657.1,7852.5 h60
  text "Board Layer Stack" at 13226.96,7852.5 h60
  text "Board Layer Stack" at 14346.65,7852.5 h60
  text "Layer" at 9797.84,7830 h60
  text "Name" at 10207.76,7830 h60
  text "Material" at 11137.5,7830 h60
  text "Thickness" at 11997.27,7830 h60
  text "Constant" at 12647.1,7830 h60
  text "Board Layer Stack" at 13216.96,7830 h60
  text "Top Overlay" at 10217.76,7732.5 h60
  text "1" at 9797.84,7710 h60
  text "Top Overlay" at 10207.76,7710 h60
  text "Top Solder" at 10217.76,7612.5 h60
  text "Solder Resist" at 11147.5,7612.5 h60
  text "0.40mil" at 12007.27,7612.5 h60
  text "3.5" at 12657.1,7612.5 h60
  text "2" at 9797.84,7590 h60
  text "Top Solder" at 10207.76,7590 h60
  text "Solder Resist" at 11137.5,7590 h60
  text "0.40mil" at 11997.27,7590 h60
  text "3.5" at 12647.1,7590 h60
  text "1" at 9807.84,7492.5 h60
  text "Top Layer" at 10217.76,7492.5 h60
  text "1.40mil" at 12007.27,7492.5 h60
  text "3" at 9797.84,7470 h60
  text "Top Layer" at 10207.76,7470 h60
  text "Copper" at 11137.5,7470 h60
  text "1.40mil" at 11997.27,7470 h60
  text "Dielectric1" at 10217.76,7372.5 h60
  text "FR-4" at 11147.5,7372.5 h60
  text "59.20mil" at 12007.27,7372.5 h60
  text "4.8" at 12657.1,7372.5 h60
  text "4" at 9797.84,7350 h60
  text "Dielectric1" at 10207.76,7350 h60
  text "FR-4" at 11137.5,7350 h60
  text "59.20mil" at 11997.27,7350 h60
  text "4.8" at 12647.1,7350 h60
  text "2" at 9807.84,7252.5 h60
  text "Bottom Layer" at 10217.76,7252.5 h60
  text "1.40mil" at 12007.27,7252.5 h60
  text "5" at 9797.84,7230 h60
  text "Bottom Layer" at 10207.76,7230 h60
  text "Copper" at 11137.5,7230 h60
  text "1.40mil" at 11997.27,7230 h60
  text "Bottom Solder" at 10217.76,7132.5 h60
  text "Solder Resist" at 11147.5,7132.5 h60
  text "0.40mil" at 12007.27,7132.5 h60
  text "3.5" at 12657.1,7132.5 h60
  text "6" at 9797.84,7110 h60
  text "Bottom Solder" at 10207.76,7110 h60
  text "Solder Resist" at 11137.5,7110 h60
  text "0.40mil" at 11997.27,7110 h60
  text "3.5" at 12647.1,7110 h60
  text "Bottom Overlay" at 10217.76,7012.5 h60
  text "7" at 9797.84,6990 h60
  text "Bottom Overlay" at 10207.76,6990 h60
  text ".Layer_Name" at 577,-858.49 h60
M13 Component Bodies Top:
  text ".Layer_Name" at 577,-858.49 h60
M14 Component Bodies Bottom:
  text ".Layer_Name" at 577,-858.49 h60
M15 Courtyards Top:
  text ".Layer_Name" at 577,-858.49 h60
M16 Courtyards Bottom:
  text ".Layer_Name" at 577,-858.49 h60
Drill Drawing:
  circle w10: c5363.72,3011.64 r27.63
  lines w10: 5336.09,2666.31 5391.34,2666.31 5363.72,2611.06 5336.09,2666.31 ; 5336.09,2749.19 5349.9,2749.19 5363.72,2735.38 5377.53,2749.19 5391.34,2749.19 5377.53,2763 5391.34,2776.82 5377.53,2776.82 5363.72,2790.63 5349.9,2776.82 5336.09,2776.82 5349.9,2763 5336.09,2749.19 ; 5336.09,2859.7 5391.34,2859.7 5391.34,2914.95 5336.09,2914.95 5336.09,2859.7 ; 5336.09,3122.15 5349.9,3122.15 5349.9,3108.34 5377.53,3108.34 5377.53,3122.15 5391.34,3122.15 5391.34,3149.78 5377.53,3149.78 5377.53,3163.59 5349.9,3163.59 5349.9,3149.78 5336.09,3149.78 5336.09,3122.15 ; 5336.09,3232.66 5363.72,3246.47 5391.34,3232.66 5377.53,3260.28 5391.34,3287.91 5363.72,3274.1 5336.09,3287.91 5349.9,3260.28 5336.09,3232.66
  lines w12: 5286,2573.76 8517.49,2573.76 ; 5286,3319.68 8517.49,3319.68 ; 5623.86,2449.44 5623.86,3444 ; 5955.86,2449.44 5955.86,3444 ; 6592.43,2449.44 6592.43,3444 ; 6851.57,2449.44 6851.57,3444 ; 7226.72,2449.44 7226.72,3444 ; 7951.05,2449.44 7951.05,3444 ; 5286,2449.44 8517.49,2449.44 8517.49,3444 5286,3444 5286,2449.44
  text "Symbol" at 5360.59,3356.98 h72
  text "Quantity" at 5661.16,3356.98 h72
  text "Finished Hole Size" at 5993.16,3356.98 h72
  text "Plated" at 6629.72,3356.98 h72
  text "Hole Type" at 6888.86,3356.98 h72
  text "Drill Layer Pair" at 7264.02,3356.98 h72
  text "Hole Tolerance" at 7988.35,3356.98 h72
  text "8" at 5661.16,3232.66 h60
  text "7.87mil (0.200mm)" at 5993.16,3232.66 h60
  text "PTH" at 6629.72,3232.66 h60
  text "Round" at 6888.86,3232.66 h60
  text "Top Layer - Bottom Layer" at 7264.02,3232.66 h60
  text "39" at 5661.16,3108.34 h60
  text "10.00mil (0.254mm)" at 5993.16,3108.34 h60
  text "PTH" at 6629.72,3108.34 h60
  text "Round" at 6888.86,3108.34 h60
  text "Top Layer - Bottom Layer" at 7264.02,3108.34 h60
  text "1049" at 5661.16,2984.02 h60
  text "14.00mil (0.356mm)" at 5993.16,2984.02 h60
  text "PTH" at 6629.72,2984.02 h60
  text "Round" at 6888.86,2984.02 h60
  text "Top Layer - Bottom Layer" at 7264.02,2984.02 h60
  text "3" at 5661.16,2859.7 h60
  text "16.00mil (0.406mm)" at 5993.16,2859.7 h60
  text "PTH" at 6629.72,2859.7 h60
  text "Round" at 6888.86,2859.7 h60
  text "Top Layer - Bottom Layer" at 7264.02,2859.7 h60
  text "12" at 5661.16,2735.38 h60
  text "35.00mil (0.889mm)" at 5993.16,2735.38 h60
  text "PTH" at 6629.72,2735.38 h60
  text "Round" at 6888.86,2735.38 h60
  text "Top Layer - Bottom Layer" at 7264.02,2735.38 h60
  text "27" at 5661.16,2611.06 h60
  text "35.43mil (0.900mm)" at 5993.16,2611.06 h60
  text "PTH" at 6629.72,2611.06 h60
  text "Round" at 6888.86,2611.06 h60
  text "Top Layer - Bottom Layer" at 7264.02,2611.06 h60
  text "1138 Total" at 5661.16,2486.74 h60
  text ".Layer_Name" at 577,-858.49 h60
M17 Embedded Cavity:
  text ".Layer_Name" at 577,-858.49 h60
M18 Embedded Assembly:
  text ".Layer_Name" at 577,-858.49 h60
M19 Embedded Keepout:
  text ".Layer_Name" at 577,-858.49 h60

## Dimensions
0,-400 to 1000,-400 on M2 Board Dimensions
0,0 to 3043,0 on M2 Board Dimensions
0,0 to 0,5109 on M2 Board Dimensions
